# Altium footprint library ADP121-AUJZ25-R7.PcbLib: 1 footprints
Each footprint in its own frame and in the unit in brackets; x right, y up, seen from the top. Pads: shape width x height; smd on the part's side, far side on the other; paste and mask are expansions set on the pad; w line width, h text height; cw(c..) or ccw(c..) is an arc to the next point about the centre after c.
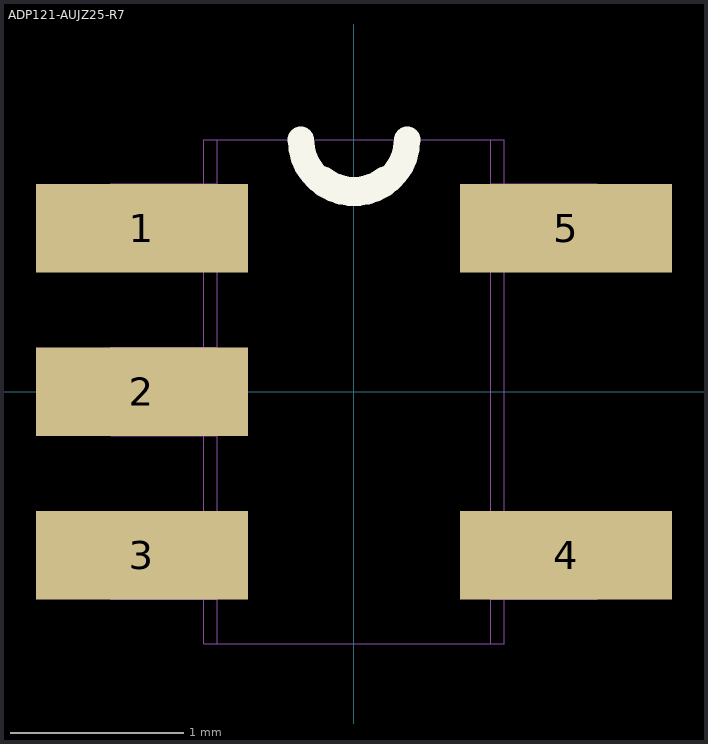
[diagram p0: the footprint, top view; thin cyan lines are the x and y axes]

## ADP121-AUJZ25-R7 [mil]
pads (5):
  rect 48x20 smd: 1(-48,37) 2(-48,0) 3(-48,-37) 4(48,-37) 5(48,37)
Top Overlay:
  lines w6: -12,57 ccw(c0,57) 12,57 ; -7,48 ccw(c0,56.96) 7,48
Mechanical 13:
  lines w0: -55,-47 -31,-47 -31,-28 -55,-28 -55,-47 ; -55,-46 -34,-46 -34,-29 -55,-29 -55,-46 ; -55,-10 -31,-10 -31,10 -55,10 -55,-10 ; -55,-9 -34,-9 -34,9 -55,9 -55,-9 ; -55,28 -31,28 -31,47 -55,47 -55,28 ; -55,29 -34,29 -34,46 -55,46 -55,29 ; -34,-57 -34,57 34,57 34,-57 -34,-57 ; -31,-57 -31,57 31,57 31,-57 -31,-57 ; -12,57 ccw(c0,57) 12,57 cw(c0,57) -12,57 ; 31,-47 55,-47 55,-28 31,-28 31,-47 ; 31,28 55,28 55,47 31,47 31,28 ; 34,-46 55,-46 55,-29 34,-29 34,-46 ; 34,29 55,29 55,46 34,46 34,29
3D body "ADP121-AUJZ25-R7.STEP": height 38.78, standoff -0.59, extent -54.81,-56.86 55.42,57.31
